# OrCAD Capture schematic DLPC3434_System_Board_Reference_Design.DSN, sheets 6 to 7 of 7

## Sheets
6 P04: MSP430 & Switches: size D
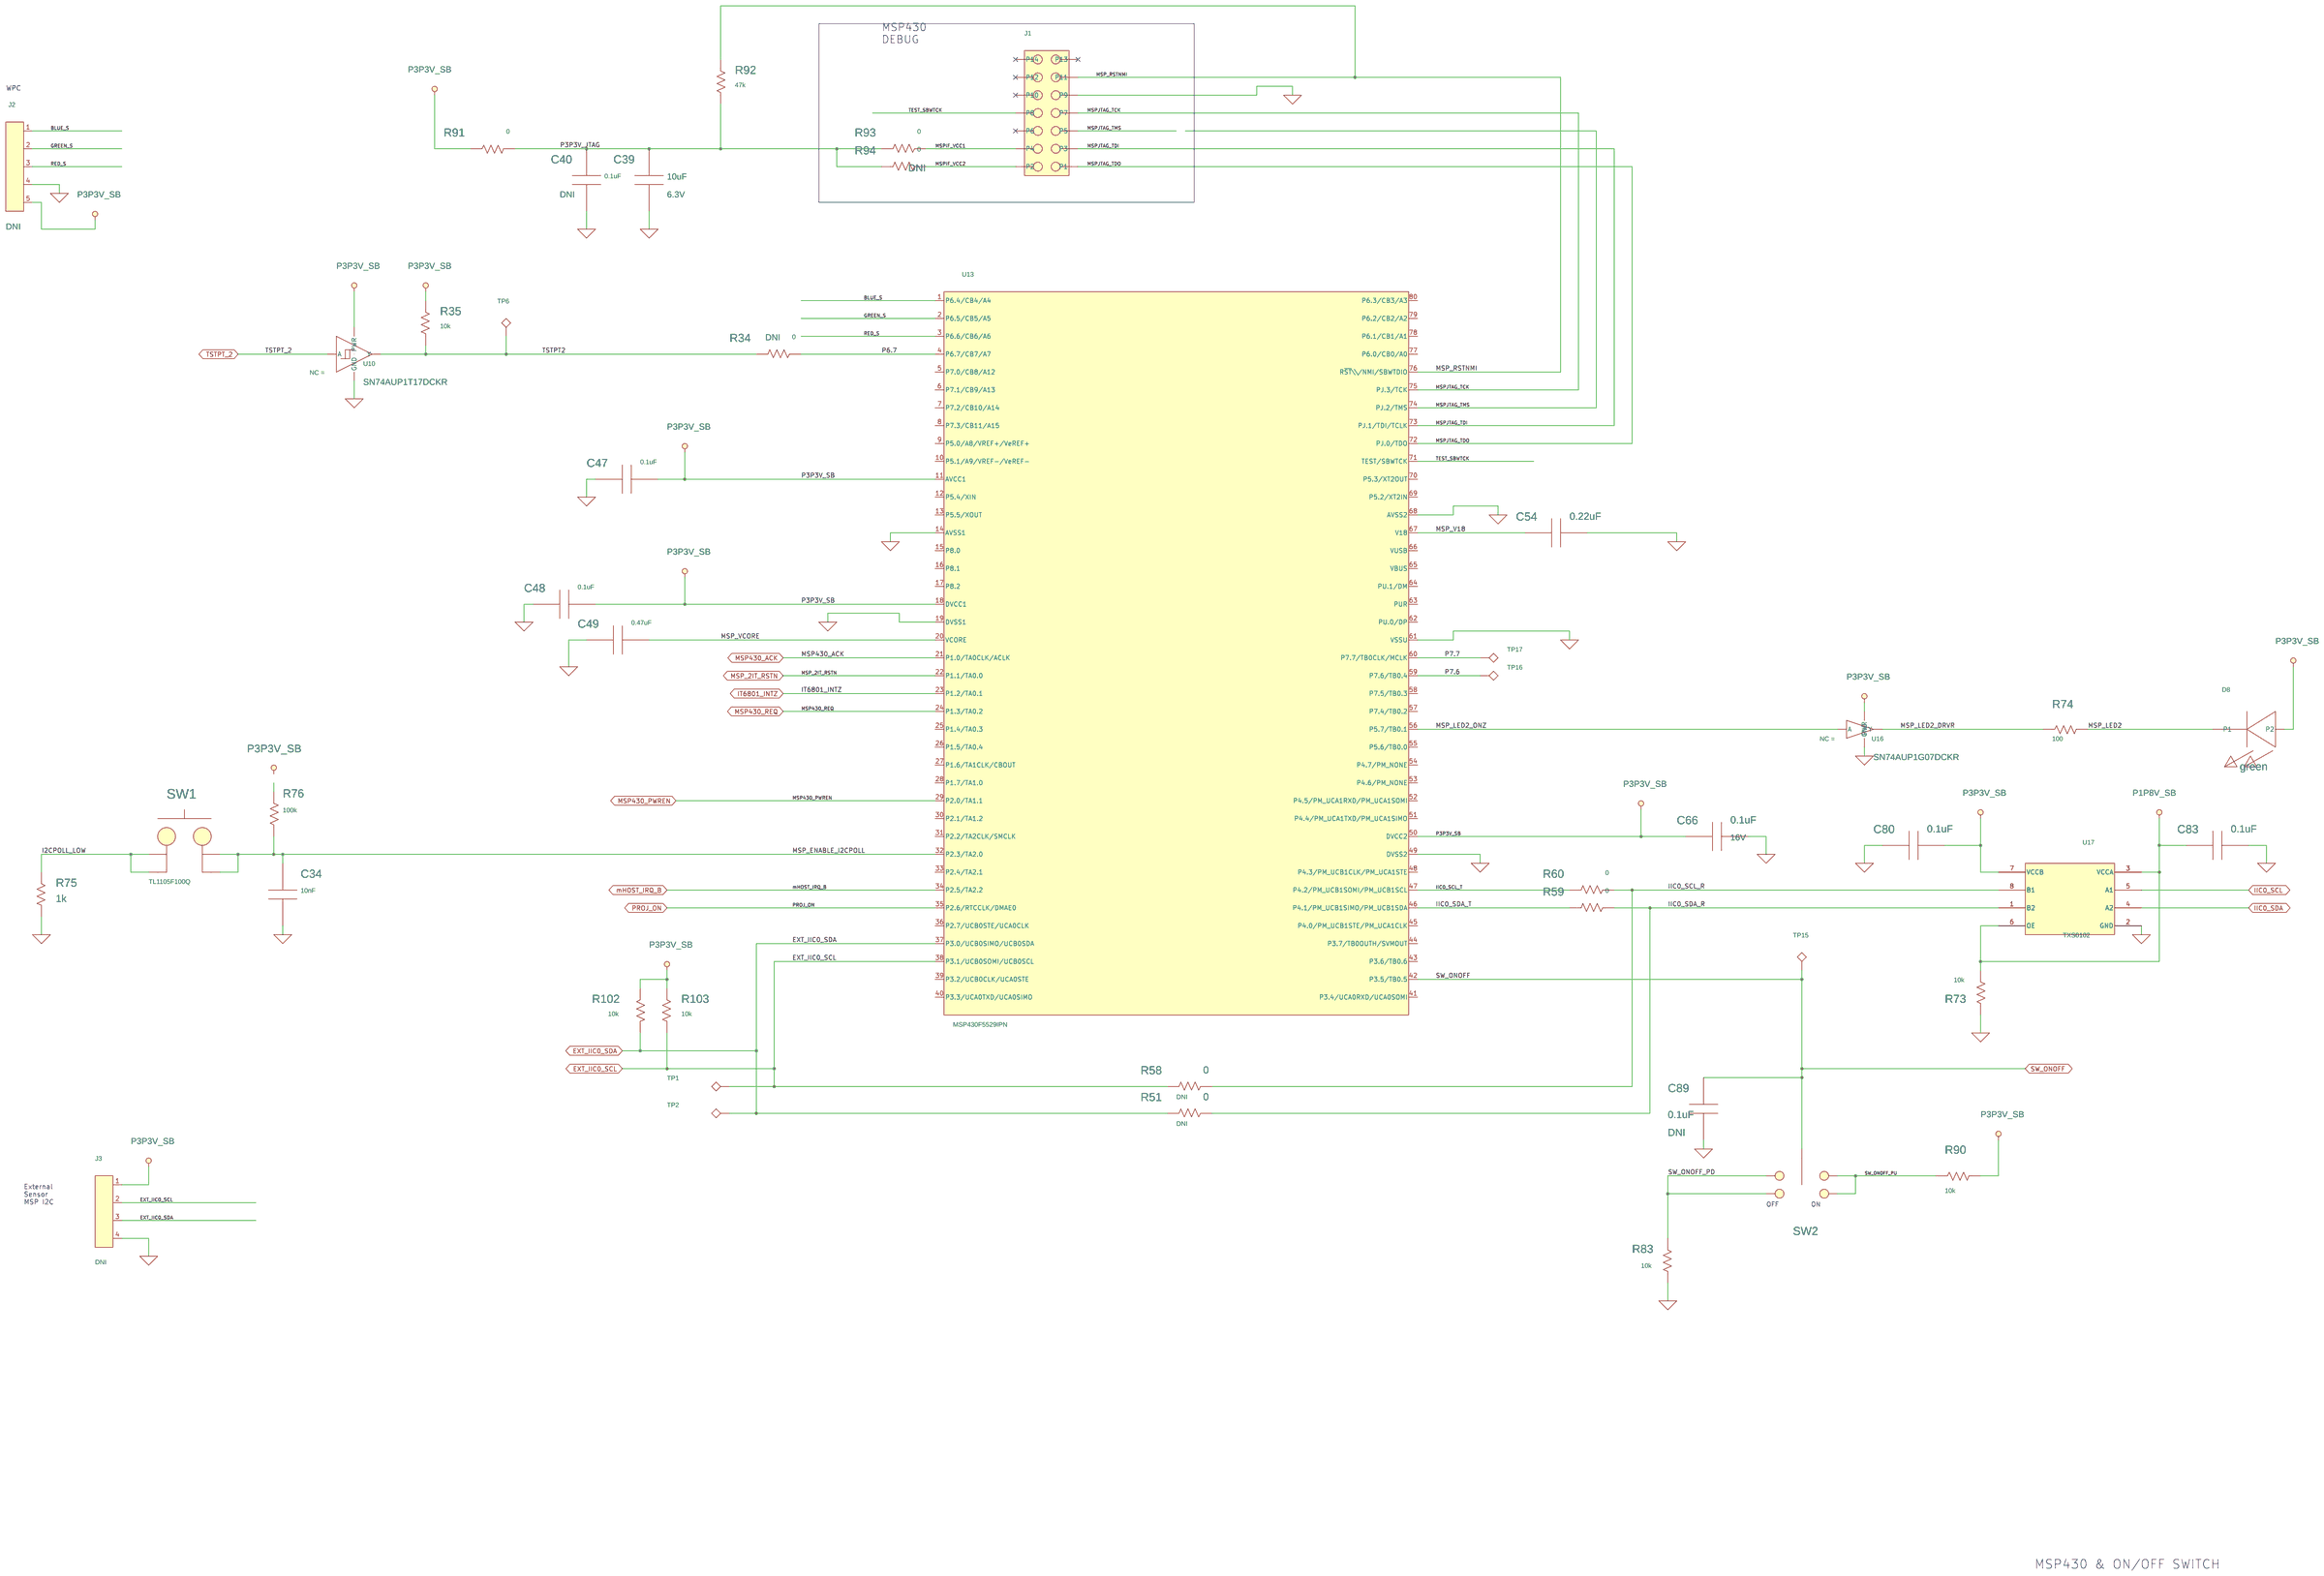
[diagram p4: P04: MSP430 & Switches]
7 P02: Display Board Connector: size D
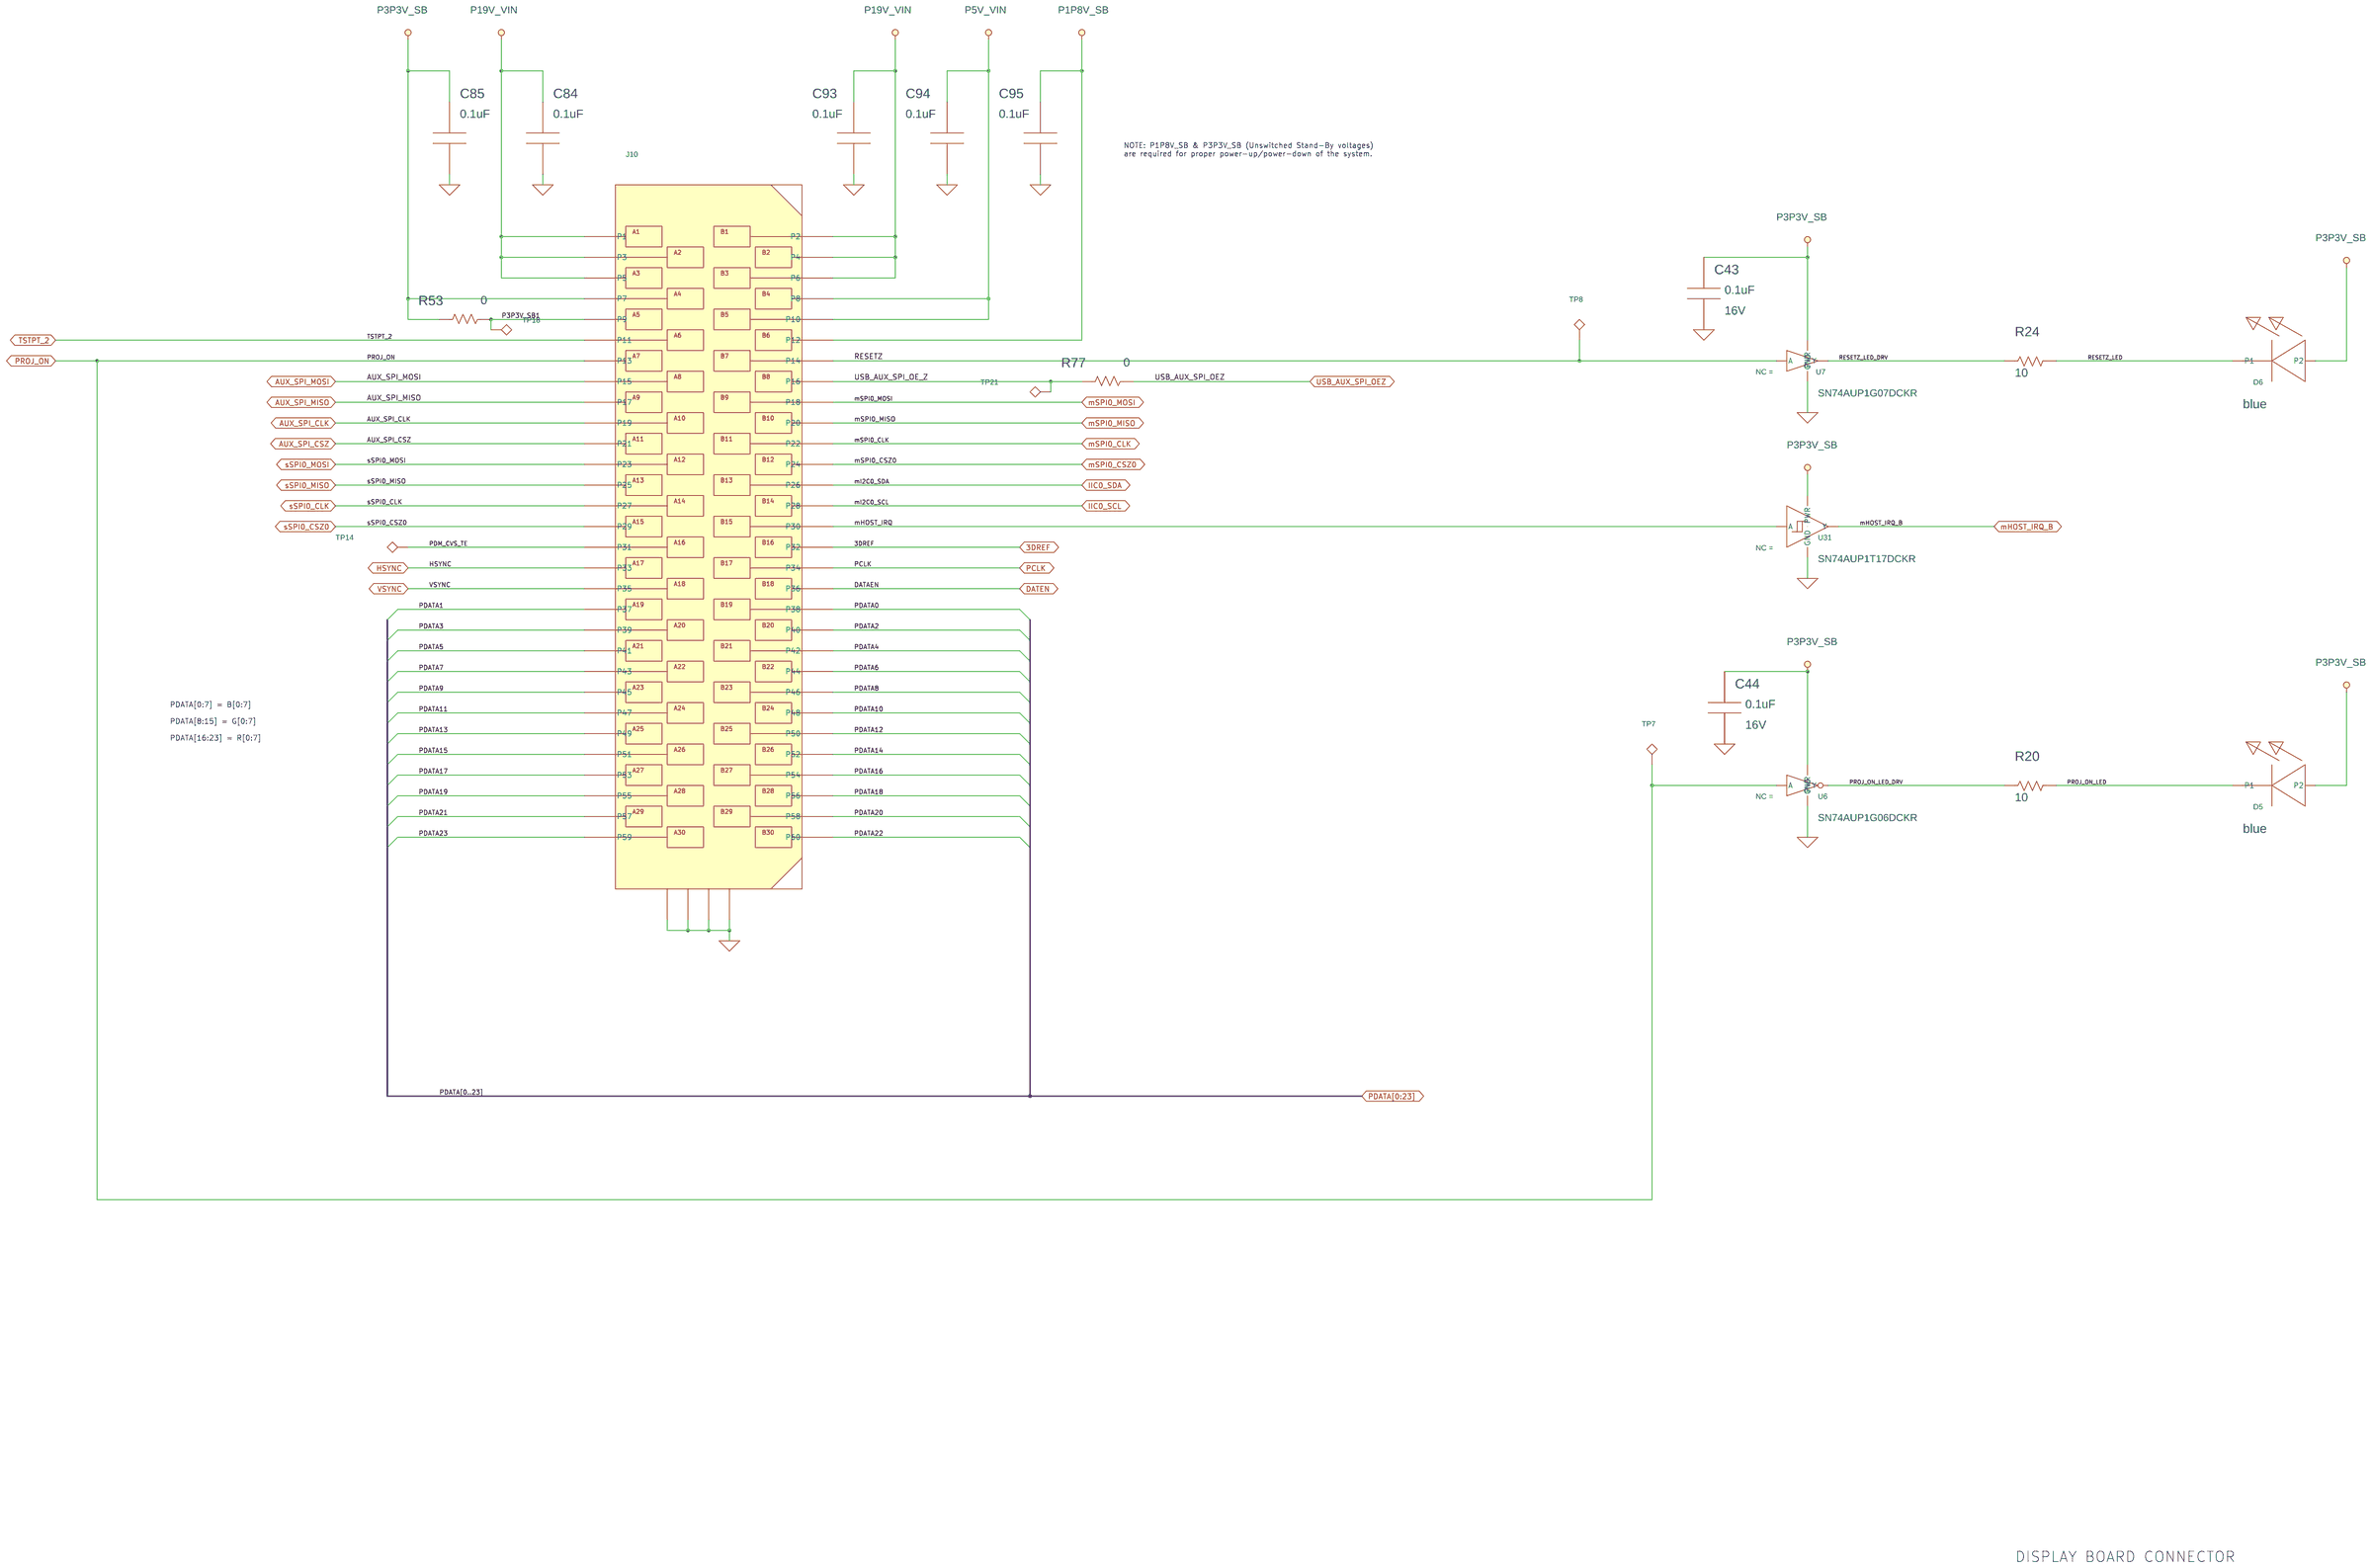
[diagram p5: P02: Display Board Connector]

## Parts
sheet P02: Display Board Connector
C43  0.1uF  [0402_AVXA]
C44  0.1uF  [0402_AVXA]
C84  0.1uF  [0402_AVXA]
C85  0.1uF  [0402_AVXA]
C93  0.1uF  [0402_AVXA]
C94  0.1uF  [0402_AVXA]
C95  0.1uF  [0402_AVXA]
D5  blue  [1206]
D6  blue  [1206]
J10  QSH-030-01-L-D-A  [Samtec_QSH-030-xx-x-D-A]
R20  10  [0402]
R24  10  [0402]
R53  0  [0402]
R77  0  [0402]
TP7  TP,40mil Drill,60mil Pad  [HOLE_PLATED_40mil_DRILL_60mil_PAD]
TP8  TP,40mil Drill,60mil Pad  [HOLE_PLATED_40mil_DRILL_60mil_PAD]
TP14  TP,40mil Drill,60mil Pad  [HOLE_PLATED_40mil_DRILL_60mil_PAD]
TP18  TP,12mil Drill,32mil Pad  [HOLE_PLATED_12mil_DRILL_32mil_PAD]
TP21  TP,12mil Drill,32mil Pad  [HOLE_PLATED_12mil_DRILL_32mil_PAD]
U6  SN74AUP1G06DCK  [U_5_DCK]
U7  SN74AUP1G07DCK  [U_5_DCK]
U31  SN74AUP1T17DCK  [SC70_5_DCK]
sheet P04: MSP430 & Switches
C34  10nF  [0402]
C39  10uF  [0603]
C40  0.1uF  [0402_AVXA]
C47  0.1uF  [0402_AVXA]
C48  0.1uF  [0402_AVXA]
C49  0.47uF  [0402]
C54  0.22uF  [0402]
C66  0.1uF  [0402_AVXA]
C80  0.1uF  [0402_AVXA]
C83  0.1uF  [0402_AVXA]
C89  0.1uF  [0402_AVXA]
D8  green  [1206]
J1  SBH11-PBPC-D07-RA-BK  [SBH11-D07-RA]
J2  B5B-ZR  [JST_B5B-ZR-SM4-TF_LF_SN_P]
J3  B4B-ZR  [JST_B4B-ZR-SM4-TF_LF_SN_P]
R34  0  [0402]
R35  10k  [0402]
R51  0  [0402]
R58  0  [0402]
R59  0  [0402]
R60  0  [0402]
R73  10k  [0402]
R74  100  [0402]
R75  1k  [0402]
R76  100k  [0402]
R83  10k  [0402]
R90  10k  [0402]
R91  0  [0402]
R92  47k  [0402]
R93  0  [0402]
R94  0  [0402]
R102  10k  [0402]
R103  10k  [0402]
SW1  TL1105F100Q  [TL1105F100Q]
SW2  GT11MSCBE  [GT11MSCBE]
TP1  TP,40mil Drill,60mil Pad  [HOLE_PLATED_40mil_DRILL_60mil_PAD]
TP2  TP,40mil Drill,60mil Pad  [HOLE_PLATED_40mil_DRILL_60mil_PAD]
TP6  TP,40mil Drill,60mil Pad  [HOLE_PLATED_40mil_DRILL_60mil_PAD]
TP15  TP,40mil Drill,60mil Pad  [HOLE_PLATED_40mil_DRILL_60mil_PAD]
TP16  TP,12mil Drill,32mil Pad  [HOLE_PLATED_12mil_DRILL_32mil_PAD]
TP17  TP,12mil Drill,32mil Pad  [HOLE_PLATED_12mil_DRILL_32mil_PAD]
U10  SN74AUP1T17DCK  [SC70_5_DCK]
U13  MSP430F5529IPN  [80-LQFP_PN_S-PQFP-G80]
U16  SN74AUP1G07DCK  [U_5_DCK]
U17  TXS0102  [VSSOP-8_DCU]

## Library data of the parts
C43 C44 C47 C48 C66 C80 C83-C85 C93-C95 = PAS,CAP,NP,large: DigiKey: 445-4952-1-ND; DigiReel: 445-4952-6-ND; Family: passive; Index PN: 681; Lead Style: SMT; MFG: TDK; Material: x7r; P/D_NUM: C1005X7R1C104K050BC; Part Number: C1005X7R1C104K050BC; Part Specific: CAP CER .1UF 16V X7R 0402; TOLERANCE: 10%; Type: capacitor; VENDOR: TDK; VPC: 16V
D5 D6 = PAS,DIODE,LED,large: DigiKey: 67-1701-1-ND; DigiReel: 67-1701-6-ND; Family: passive; Index PN: 1250; Install: Y; Lead Style: SMT; MFG: Lumex; P/D_NUM: SML-LX1206USBC-TR; Part Number: SML-LX1206USBC-TR; Part Specific: LED INGAN/SIC U-BLUE CLR 1206SMD; Type: diode,led; VENDOR: Lumex
J10 = EM,CONN,60P,QSx_2: DigiKey: SAM8180-ND; Family: electro/mechanical; Index PN: 1061; Lead Style: SMT; MFG: Samtec; Part Specific: CONN RCPT HI-SPD .5MM 60POS DL (stacking ht 5mm); Pin Cnt: 60; Pin Spacing: 0.5mm; Row Cnt: 2; Type: connector; Vendor: Samtec
R20 R24 = PAS,R,large: DigiKey: P10.0LCT-ND; DigiReel: P10.0LDKR-ND; Family: passive; Index PN: 1099; Lead Style: SMT; MFG: Panasonic; Material: chip; P/D_NUM: ERJ-2RKF10R0X; Part Number: ERJ-2RKF10R0X; Part Specific: RES 10.0 OHM 1/10W 1% 0402 SMD; TOLERANCE: 1%; Type: resistor; VENDOR: Panasonic; VPC: 1/10W
R53 R59 R60 R77 R93 = PAS,R,large: DigiKey: P0.0JCT-ND; DigiReel: P0.0JDKR-ND; Family: passive; Index PN: 687; Install: Y; Lead Style: SMT; MFG: Panasonic; Material: chip; P/D_NUM: ERJ-2GE0R00X; Part Number: ERJ-2GE0R00X; Part Specific: RES 0.0 OHM 1/16W 0402 SMD; Power: 1/16W; Type: resistor; VPC: 1/16W; Vendor: Panasonic
TP1 TP2 TP6-TP8 TP14 TP15 = BF,HOLE,PLATED,TESTPIN: DigiKey: ---; DigiReel: ---; Family: board feature; Index PN: 377; Install: DNI; Lead Style: TH; MFG: -- NOT A PART --; Type: hole,plated; Vendor: -- NOT A PART --
TP16-TP18 TP21 = EM,TERM,TESTPOINT: Family: board feature; Index PN: 122; Install: DNI; MFG: -- NOT A PART --; Type: hole,plated; Vendor: -- NOT A PART --
U6 = TMP_153924: DigiKey: 296-17562-1-ND; DigiReel: 296-17562-6-ND; Family: logic; Index PN: 1026; Lead Style: SMT; MFG: Texas Instruments; P/D_NUM: SN74AUP1G06DCKR; Part Number: SN74AUP1G06DCKR; Part Specific: IC INVERTER SINGLE 1INPUT SC705, open drain; Type: buffer
U7 U16 = TMP_153900: DigiKey: 296-18256-1-ND; DigiReel: 296-18256-6-ND; Family: logic; Index PN: 1027; Install: Y; Lead Style: SMT; MFG: Texas Instruments; P/D_NUM: SN74AUP1G07DCKR; Part Number: SN74AUP1G07DCKR; Part Specific: IC BUFF/DVR LOW PWR N-INV SC705, open drain; Type: buffer
U10 U31 = LOG_BUFF,AUP1T17: DigiKey: 296-27395-1-ND; DigiReel: 296-27395-6-ND; Family: logic; Lead Style: SMT; MFG: Texas Instruments; P/D_NUM: SN74AUP1T17DCKR; Part Number: SN74AUP1T17DCKR; Part Specific: IC BUFFER SCHMITT TRIG LP SC70-5; Type: buffer
C34 = PAS,CAP,NP,large: DigiKey: 490-1312-1-ND; DigiReel: 490-1312-6-ND; Family: passive; Install: Y; Lead Style: SMT; MFG: Murata; Material: X7R; P/D_NUM: GRM155R71E103KA01D; Part Number: GRM155R71E103KA01D; Part Specific: 10000pF 25V Ceramic Capacitor X7R 0402; TOLERANCE: 10%; Type: capacitor; VENDOR: Murata; VPC: 25V
C39 = PAS,CAP,NP,large: DigiKey: 445-4112-1-ND; DigiReel: 445-4112-6-ND; Family: passive; Index PN: 906; Lead Style: SMT; MFG: TDK; Material: x5r; P/D_NUM: C1608X5R0J106M080AB; Part Number: C1608X5R0J106M080AB; Part Specific: CAP CERAMIC 10UF 6.3V X5R 0603; Tolerance: 20%; Type: capacitor; VENDOR: TDK; VPC: 6.3V
C40 C89 = PAS,CAP,NP,large: DigiKey: 445-4952-1-ND; DigiReel: 445-4952-6-ND; Family: passive; Index PN: 681; Install: DNI; Lead Style: SMT; MFG: TDK; Material: x7r; P/D_NUM: C1005X7R1C104K050BC; Part Number: C1005X7R1C104K050BC; Part Specific: CAP CER .1UF 16V X7R 0402; TOLERANCE: 10%; Type: capacitor; VENDOR: TDK; VPC: 16V
C49 = PAS,CAP,NP,large: DigiKey: 445-13864-1-ND; DigiReel: 445-13864-6-ND; Family: passive; Index PN: 1284; Lead Style: SMT; MFG: TDK; P/D_NUM: C1005X5R1V474K050BC; Part Number: C1005X5R1V474K050BC; Part Specific: CAP CER 0.47UF 35V 10% X5R 0402; TOLERANCE: 10%; Type: capacitor; VENDOR: TDK; VPC: 35V
C54 = PAS,CAP,NP,large: DigiKey: 587-2475-1-ND; DigiReel: 587-2475-6-ND; Family: passive; Index PN: 905; Lead Style: SMT; MFG: Taiyo Yuden; Material: x7r; P/D_NUM: JMK105B7224KV-F; Part Number: JMK105B7224KV-F; Part Specific: CAP CER .22UF 6.3V X7R 10% 0402; TOLERANCE: 10%; Type: capacitor; VENDOR: Taiyo Yuden; VPC: 6.3V
D8 = PAS,DIODE,LED,large: DigiKey: 67-1357-1-ND; DigiReel: 67-1357-6-ND; Family: passive; Index PN: 31; Install: Y; Lead Style: SMT; MFG: Lumex; P/D_NUM: SML-LX1206GC-TR; Part Number: SML-LX1206GC-TR; Part Specific: LED 565NM WTR CLR GREEN 1206 SMD; Type: diode,led; VENDOR: Lumex
J1 = EM,HDR,14P,2R,2X,Narrow: DigiKey: S9178-ND; DigiReel: ---; Family: electro/mechanical; Install: Y; Lead Style: TH; MFG: Sullins; Part Specific: CONN HEADER 2.54MM 14POS GOLD R/A; Pin Cnt: 14; Pin Spacing: 100x100mil; Row Cnt: 2; Type: header; VENDOR: Sullins
J2 = EM,HDR,5P,1R,2x: DigiKey: 455-1684-1-ND; DigiReel: 455-1684-6-ND; Family: electro/mechanical; Install: DNI; Lead Style: SMT; MFG: JST; P/D_NUM: B5B-ZR-SM4-TF(LF)(SN)(P); Part Number: B5B-ZR-SM4-TF(LF)(SN)(P); Part Specific: CONN HEADER ZH TOP 5POS 1.5MM; Pin Cnt: 5; Pin Spacing: 1.5mm; Row Cnt: 1; Type: header; Vendor: JST
J3 = EM,HDR,4P,1R,2x: DigiKey: 455-1683-1-ND; DigiReel: 455-1683-6-ND; Family: electro/mechanical; Install: DNI; MFG: JST; P/D_NUM: B4B-ZR-SM4-TF(LF)(SN)(P); Part Number: B4B-ZR-SM4-TF(LF)(SN)(P); Part Specific: CONN HEADER ZH TOP 4POS 1.5MM; Pin Cnt: 4; Pin Spacing: 1.5mm; Row Cnt: 1; Type: header; Vendor: JST
R34 R51 R58 R94 = PAS,R,large: DigiKey: P0.0JCT-ND; DigiReel: P0.0JDKR-ND; Family: passive; Index PN: 687; Install: DNI; Lead Style: SMT; MFG: Panasonic; Material: chip; P/D_NUM: ERJ-2GE0R00X; Part Number: ERJ-2GE0R00X; Part Specific: RES 0.0 OHM 1/16W 0402 SMD; Power: 1/16W; Type: resistor; VPC: 1/16W; Vendor: Panasonic
R35 R83 R90 R102 R103 = PAS,R,large: DigiKey: P10.0KLCT-ND; DigiReel: P10.0KLDKR-ND; Family: passive; Index PN: 680; Lead Style: SMT; MFG: Panasonic; Material: chip; P/D_NUM: ERJ-2RKF1002X; Part Number: ERJ-2RKF1002X; Part Specific: RES SMD 10K OHM 1% 1/10W 0402; Power: 1/16W; TOLERANCE: 1%; Type: resistor; VENDOR: Panasonic; VPC: 1/16W
R73 = PAS,R,large: DigiKey: P10.0KLCT-ND; DigiReel: P10.0KLDKR-ND; Family: passive; Index PN: 680; Install: Y; Lead Style: SMT; MFG: Panasonic; Material: chip; P/D_NUM: ERJ-2RKF1002X; Part Number: ERJ-2RKF1002X; Part Specific: RES SMD 10K OHM 1% 1/10W 0402; Power: 1/16W; TOLERANCE: 1%; Type: resistor; VPC: 1/16W; Vendor: Panasonic
R74 = PAS,R,large: DigiKey: P100LCT-ND; DigiReel: P100LDKR-ND; Family: passive; Index PN: 690; Lead Style: SMT; MFG: Panasonic; Material: chip; P/D_NUM: ERJ-2RKF1000X; Part Number: ERJ-2RKF1000X; Part Specific: RES 100 OHM 1/10W 1% 0402 SMD; Power: 1/16W; TOLERANCE: 1%; Type: resistor; VENDOR: Panasonic; VPC: 1/16W
R75 = PAS,R,large: DigiKey: 311-1.00KLRCT-ND; DigiReel: 311-1.00KLRDKR-ND; Family: passive; Install: Y; Lead Style: SMT; MFG: Yageo; Material: chip; P/D_NUM: RC0402FR-071KL; Part Number: RC0402FR-071KL; Part Specific: RES SMD 1K OHM 1% 1/16W 0402; Power: 1/16W; TOLERANCE: 1%; Type: resistor; VPC: 1/16W; Vendor: Yageo
R76 = PAS,R,large: DigiKey: 541-100KLCT-ND; DigiReel: 541-100KLDKR-ND; Family: passive; Lead Style: SMT; MFG: Vishay Dale; P/D_NUM: CRCW0402100KFKED; Part Number: CRCW0402100KFKED; Part Specific: RES SMD 100K OHM 1% 1/16W 0402; TOLERANCE: 1%; Type: Resistor; VENDOR: Vishay Dale; VPC: 1/16W
R91 = PAS,R,large: DigiKey: P0.0JCT-ND; DigiReel: P0.0JDKR-ND; Family: passive; Index PN: 687; Lead Style: SMT; MFG: Panasonic; Material: chip; P/D_NUM: ERJ-2GE0R00X; Part Number: ERJ-2GE0R00X; Part Specific: RES 0.0 OHM 1/16W 0402 SMD; Power: 1/16W; Type: resistor; VPC: 1/16W; Vendor: Panasonic
R92 = PAS,R,large: DigiKey: P47.0KLCT-ND; DigiReel: P47.0KLDKR-ND; Family: passive; Index PN: 1030; Lead Style: SMT; MFG: Panasonic; Material: chip; P/D_NUM: ERJ-2RKF4702X; Part Number: ERJ-2RKF4702X; Part Specific: RES 47.0K OHM 1/10W 1% 0402 SMD; Type: resistor; VPC: 1/16W; Vendor: Panasonic
SW1 = SWITCH_TACTILE_SPST-NO: DigiKey: EG2494-ND; DigiReel: ---; Family: electro/mechanical; Install: Y; Lead Style: TH; Part Specific: SWITCH TACTILE SPST-NO 0.05A 12V TH; Type: Switch; Vendor: E-Switch
SW2 = EM,SW,SPDT,GT11: DigiKey: CKN1784CT-ND; DigiReel: CKN1784DKR-ND; Family: electro/mechanical; Index PN: 1035; Install: Y; Lead Style: SMT; MFG: C&K; Part Specific: SWITCH TOGGLE SPDT ULTRAMINI SMD; Type: switch; Vendor: C&K
U13 = TMP_3: DigiKey: 296-25427-ND; DigiReel: ---; Family: processor; Index PN: 1343; Lead Style: SMT; MFG: Texas Instruments; Part Specific: IC MCU 16BIT 128KB FLASH 80LQFP; Type: microcontroller; Vendor: Texas Instruments; Voltage: 1.8 V ~ 3.6 V
U17 = TXS0102: DigiKey: 296-21931-1-ND; DigiReel: 296-21931-6-ND; Family: interface; Index PN: 877; Install: Y; Lead Style: SMT; MFG: Texas Instruments; P/D_NUM: TXS0102DCUR; Part Number: TXS0102DCUR; Part Specific: IC VOLT-LEVEL TRANSLATOR 8-US8; Type: driver; VENDOR: Texas Instruments

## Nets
DGND: C34.2(N) C39.2(N) C40.2(N) C43.2(N) C44.2(N) C47.2(N) C48.2(N) C49.2(N) C54.1(P) C66.1(P) C80.1(P) C83.2(N) C84.2(N) C85.2(N) C89.2(N) C93.2(N) C94.2(N) C95.2(N) J1.9(P9) J2.4 J3.4 J10.G1 J10.G2 J10.G3 J10.G4 R73.2(N2) R75.1(N1) R83.1(N1) U6.3(GND) U7.3(GND) U10.3(GND) U13.14(AVSS1) U13.19(DVSS1) U13.49(DVSS2) U13.61(VSSU) U13.68(AVSS2) U16.3(GND) U17.2(GND) U31.3(GND) ; also on sheet 3 4 5
P5V_VIN: C94.1(P) J10.8(P8) J10.10(P10) ; also on sheet 3 4
P19V_VIN: C84.1(P) C93.1(P) J10.1(P1) J10.2(P2) J10.3(P3) J10.4(P4) J10.5(P5) J10.6(P6) ; also on sheet 3
3DREF: J10.32(P32) ; also on sheet 4
AUX_SPI_CLK: J10.19(P19) ; also on sheet 5
AUX_SPI_CSZ: J10.21(P21) ; also on sheet 5
AUX_SPI_MISO: J10.17(P17) ; also on sheet 5
AUX_SPI_MOSI: J10.15(P15) ; also on sheet 5
BLUE_S: J2.1 U13.1(P6.4/CB4/A4)
DATEN: J10.36(P36) ; also on sheet 4
EXT_IIC0_SCL: J3.2 R58.1(N1) R103.1(N1) TP1.1(P1) U13.38(P3.1/UCB0SOMI/UCB0SCL) ; also on sheet 4
EXT_IIC0_SDA: J3.3 R51.1(N1) R102.1(N1) TP2.1(P1) U13.37(P3.0/UCB0SIMO/UCB0SDA) ; also on sheet 4
GREEN_S: J2.2 U13.2(P6.5/CB5/A5)
HSYNC: J10.33(P33) ; also on sheet 4
I2CPOLL_LOW: R75.2(N2) SW1.1 SW1.2
IIC0_SCL: J10.28(P28) U17.5(A1) ; also on sheet 5
IIC0_SCL_R: R58.2(N2) R60.2(N2) U17.8(B1)
IIC0_SCL_T: R60.1(N1) U13.47(P4.2/PM_UCB1SOMI/PM_UCB1SCL)
IIC0_SDA: J10.26(P26) U17.4(A2) ; also on sheet 5
IIC0_SDA_R: R51.2(N2) R59.2(N2) U17.1(B2)
IIC0_SDA_T: R59.1(N1) U13.46(P4.1/PM_UCB1SIMO/PM_UCB1SDA)
IT6801_INTZ: U13.23(P1.2/TA0.1) ; also on sheet 4
mHOST_IRQ: J10.30(P30) U31.2(A)
mHOST_IRQ_B: U13.34(P2.5/TA2.2) U31.4(Y) ; also on sheet 5
MSP430_ACK: U13.21(P1.0/TA0CLK/ACLK) ; also on sheet 5
MSP430_PWREN: U13.29(P2.0/TA1.1) ; also on sheet 3
MSP430_REQ: U13.24(P1.3/TA0.2) ; also on sheet 5
MSP_2IT_RSTN: U13.22(P1.1/TA0.0) ; also on sheet 4
MSP_ENABLE_I2CPOLL: C34.1(P) R76.2(N2) SW1.3 SW1.4 U13.32(P2.3/TA2.0)
MSP_LED2: D8.1(P1) R74.1(N1)
MSP_LED2_DRVR: R74.2(N2) U16.4(Y)
MSP_LED2_ONZ: U13.56(P5.7/TB0.1) U16.2(A)
MSP_RSTNMI: J1.11(P11) R92.1(N1) U13.76(R~{ST}\\/NMI/SBWTDIO)
MSP_V18: C54.2(N) U13.67(V18)
MSP_VCORE: C49.1(P) U13.20(VCORE)
mSPI0_CLK: J10.22(P22) ; also on sheet 5
mSPI0_CSZ0: J10.24(P24) ; also on sheet 5
mSPI0_MISO: J10.20(P20) ; also on sheet 5
mSPI0_MOSI: J10.18(P18) ; also on sheet 5
MSPIF_VCC1: J1.4(P4) R93.2(N2)
MSPIF_VCC2: J1.2(P2) R94.2(N2)
MSPJTAG_TCK: J1.7(P7) U13.75(PJ.3/TCK)
MSPJTAG_TDI: J1.3(P3) U13.73(PJ.1/TDI/TCLK)
MSPJTAG_TDO: J1.1(P1) U13.72(PJ.0/TDO)
MSPJTAG_TMS: J1.5(P5) U13.74(PJ.2/TMS)
P1P8V_SB: C83.1(P) C95.1(P) J10.12(P12) R73.1(N1) U17.3(VCCA) U17.6(OE) ; also on sheet 3 5
P3P3V_JTAG: C39.1(P) C40.1(P) R91.1(N1) R92.2(N2) R93.1(N1) R94.1(N1)
P3P3V_SB: C43.1(P) C44.1(P) C47.1(P) C48.1(P) C66.2(N) C80.2(N) C85.1(P) D5.2(P2) D6.2(P2) D8.2(P2) J2.5 J3.1 J10.7(P7) R35.2(N2) R53.1(N1) R76.1(N1) R90.1(N1) R91.2(N2) R102.2(N2) R103.2(N2) U6.5(PWR) U7.5(PWR) U10.5(PWR) U13.11(AVCC1) U13.18(DVCC1) U13.50(DVCC2) U16.5(PWR) U17.7(VCCB) U31.5(PWR) ; also on sheet 3 4 5
P3P3V_SB1: J10.9(P9) R53.2(N2) TP18.1(P1)
P6.7: R34.2(N2) U13.4(P6.7/CB7/A7)
P7.6: TP16.1(P1) U13.59(P7.6/TB0.4)
P7.7: TP17.1(P1) U13.60(P7.7/TB0CLK/MCLK)
PCLK: J10.34(P34) ; also on sheet 4
PDATA0: J10.38(P38) ; also on sheet 4
PDATA1: J10.37(P37) ; also on sheet 4
PDATA2: J10.40(P40) ; also on sheet 4
PDATA3: J10.39(P39) ; also on sheet 4
PDATA4: J10.42(P42) ; also on sheet 4
PDATA5: J10.41(P41) ; also on sheet 4
PDATA6: J10.44(P44) ; also on sheet 4
PDATA7: J10.43(P43) ; also on sheet 4
PDATA8: J10.46(P46) ; also on sheet 4
PDATA9: J10.45(P45) ; also on sheet 4
PDATA10: J10.48(P48) ; also on sheet 4
PDATA11: J10.47(P47) ; also on sheet 4
PDATA12: J10.50(P50) ; also on sheet 4
PDATA13: J10.49(P49) ; also on sheet 4
PDATA14: J10.52(P52) ; also on sheet 4
PDATA15: J10.51(P51) ; also on sheet 4
PDATA16: J10.54(P54) ; also on sheet 4
PDATA17: J10.53(P53) ; also on sheet 4
PDATA18: J10.56(P56) ; also on sheet 4
PDATA19: J10.55(P55) ; also on sheet 4
PDATA20: J10.58(P58) ; also on sheet 4
PDATA21: J10.57(P57) ; also on sheet 4
PDATA22: J10.60(P60) ; also on sheet 4
PDATA23: J10.59(P59) ; also on sheet 4
PDM_CVS_TE: J10.31(P31) TP14.1(P1)
PROJ_ON: J10.13(P13) TP7.1(P1) U6.2(A) U13.35(P2.6/RTCCLK/DMAE0)
PROJ_ON_LED: D5.1(P1) R20.1(N1)
PROJ_ON_LED_DRV: R20.2(N2) U6.4(Y)
RED_S: J2.3 U13.3(P6.6/CB6/A6)
RESETZ: J10.14(P14) TP8.1(P1) U7.2(A)
RESETZ_LED: D6.1(P1) R24.1(N1)
RESETZ_LED_DRV: R24.2(N2) U7.4(Y)
sSPI0_CLK: J10.27(P27) ; also on sheet 5
sSPI0_CSZ0: J10.29(P29) ; also on sheet 5
sSPI0_MISO: J10.25(P25) ; also on sheet 5
sSPI0_MOSI: J10.23(P23) ; also on sheet 5
SW_ONOFF: C89.1(P) SW2.2 TP15.1(P1) U13.42(P3.5/TB0.5) ; also on sheet 5
SW_ONOFF_PD: R83.2(N2) SW2.1 SW2.4
SW_ONOFF_PU: R90.2(N2) SW2.3 SW2.6
TEST_SBWTCK: J1.8(P8) U13.71(TEST/SBWTCK)
TSTPT2: R34.1(N1) R35.1(N1) TP6.1(P1) U10.4(Y)
TSTPT_2: J10.11(P11) U10.2(A)
USB_AUX_SPI_OE_Z: J10.16(P16) R77.1(N1) TP21.1(P1)
USB_AUX_SPI_OEZ: R77.2(N2) ; also on sheet 5
VSYNC: J10.35(P35) ; also on sheet 4

Not connected (* = marked no-connect by the designer): J1 6(P6)* 10(P10)* 12(P12)* 13(P13)* 14(P14)*; U13 5(P7.0/CB8/A12) 6(P7.1/CB9/A13) 7(P7.2/CB10/A14) 8(P7.3/CB11/A15) 9(P5.0/A8/VREF+/VeREF+) 10(P5.1/A9/VREF-/VeREF-) 12(P5.4/XIN) 13(P5.5/XOUT) 15(P8.0) 16(P8.1) 17(P8.2) 25(P1.4/TA0.3) 26(P1.5/TA0.4) 27(P1.6/TA1CLK/CBOUT) 28(P1.7/TA1.0) 30(P2.1/TA1.2) 31(P2.2/TA2CLK/SMCLK) 33(P2.4/TA2.1) 36(P2.7/UCB0STE/UCA0CLK) 39(P3.2/UCB0CLK/UCA0STE) 40(P3.3/UCA0TXD/UCA0SIMO) 41(P3.4/UCA0RXD/UCA0SOMI) 43(P3.6/TB0.6) 44(P3.7/TB0OUTH/SVMOUT) 45(P4.0/PM_UCB1STE/PM_UCA1CLK) 48(P4.3/PM_UCB1CLK/PM_UCA1STE) 51(P4.4/PM_UCA1TXD/PM_UCA1SIMO) 52(P4.5/PM_UCA1RXD/PM_UCA1SOMI) 53(P4.6/PM_NONE) 54(P4.7/PM_NONE) 55(P5.6/TB0.0) 57(P7.4/TB0.2) 58(P7.5/TB0.3) 62(PU.0/DP) 63(PUR) 64(PU.1/DM) 65(VBUS) 66(VUSB) 69(P5.2/XT2IN) 70(P5.3/XT2OUT) 77(P6.0/CB0/A0) 78(P6.1/CB1/A1) 79(P6.2/CB2/A2) 80(P6.3/CB3/A3)

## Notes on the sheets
sheet 6
- MSP430
  DEBUG
- WPC
- External
  Sensor
  MSP I2C
- OFF
- ON
- MSP430 & ON/OFF SWITCH
sheet 7
- NOTE: P1P8V_SB & P3P3V_SB (Unswitched Stand-By voltages)
  are required for proper power-up/power-down of the system.
- PDATA[0:7] = B[0:7]
  PDATA[8:15] = G[0:7]
  PDATA[16:23] = R[0:7]
- DISPLAY BOARD CONNECTOR
